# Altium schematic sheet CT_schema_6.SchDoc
size 278 x 170 mm
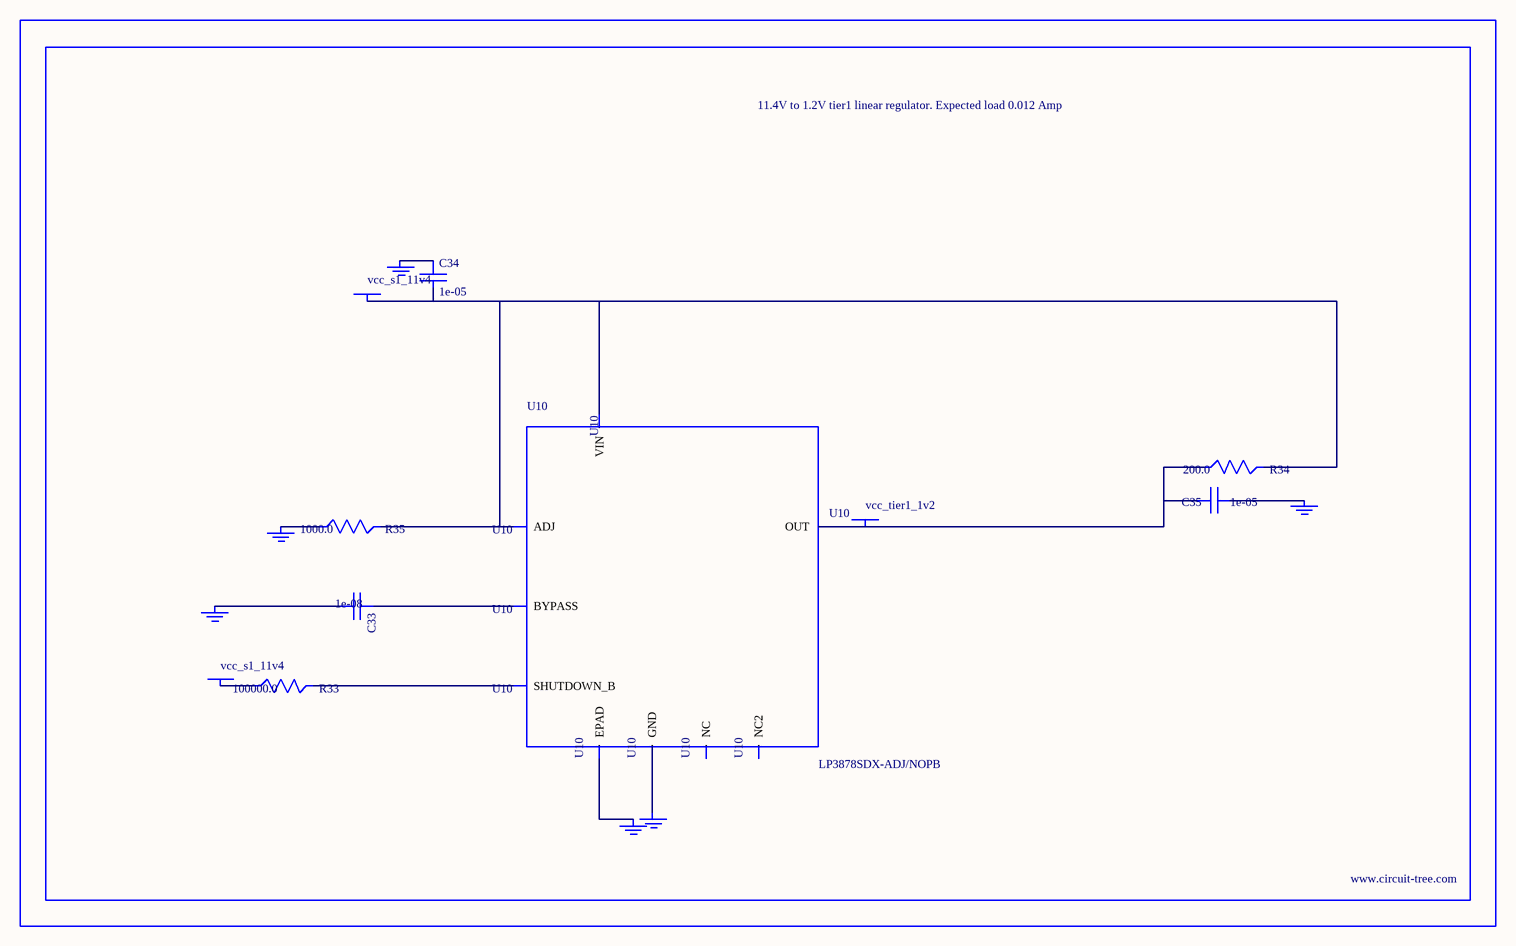
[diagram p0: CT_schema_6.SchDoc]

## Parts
BORDER5  (no value)
C33  1e-08  [C0402]
C34  1e-05  [C1210]
C35  1e-05  [C0805]
GND_INSTANCE_5_0  (no value)
GND_INSTANCE_5_1  (no value)
GND_INSTANCE_5_2  (no value)
GND_INSTANCE_5_3  (no value)
GND_INSTANCE_5_4  (no value)
GND_INSTANCE_5_5  (no value)
POWER_INSTANCE_5_0  vcc_s1_11v4
POWER_INSTANCE_5_1  vcc_s1_11v4
POWER_INSTANCE_5_2  vcc_tier1_1v2
R33  100000.0  [R0603]
R34  200.0  [R0603]
R35  1000.0  [R0603]
U10  LP3878SDX-ADJ/NOPB  [WSON-8]

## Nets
NetC33_1: C33.1 U10.1(BYPASS)
NetC33_2: C33.2 GND_INSTANCE_5_0.0(GND)
NetC34_1: C34.1 GND_INSTANCE_5_1.0(GND)
NetC34_2: C34.2 POWER_INSTANCE_5_0.0(PWR) R34.2 R35.2 U10.4(VIN) U10.6(ADJ)
NetC35_1: C35.1 GND_INSTANCE_5_2.0(GND)
NetC35_2: C35.2 POWER_INSTANCE_5_2.0(PWR) R34.1 U10.5(OUT)
NetGND_INSTANCE_5_3_0: GND_INSTANCE_5_3.0(GND) R35.1
NetGND_INSTANCE_5_4_0: GND_INSTANCE_5_4.0(GND) U10.PAD(EPAD)
NetGND_INSTANCE_5_5_0: GND_INSTANCE_5_5.0(GND) U10.3(GND)
NetPOWER_INSTANCE_5_1_0: POWER_INSTANCE_5_1.0(PWR) R33.1
NetR33_2: R33.2 U10.8(SHUTDOWN_B)

Not connected (* = marked no-connect by the designer): U10 2(NC) 7(NC2)

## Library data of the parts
BORDER5 = BORDER_PAGE5
C33 = C0402C103K3RAC
C34 = C1210C106K5PACTU
C35 = GRM219R60J106ME19D
GND_INSTANCE_5_0-GND_INSTANCE_5_5 = GND
POWER_INSTANCE_5_0-POWER_INSTANCE_5_2 = PWR
R33 = RC0603JR-07100KL
R34 = RC0603JR-07200RL
R35 = RC0603JR-071KL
